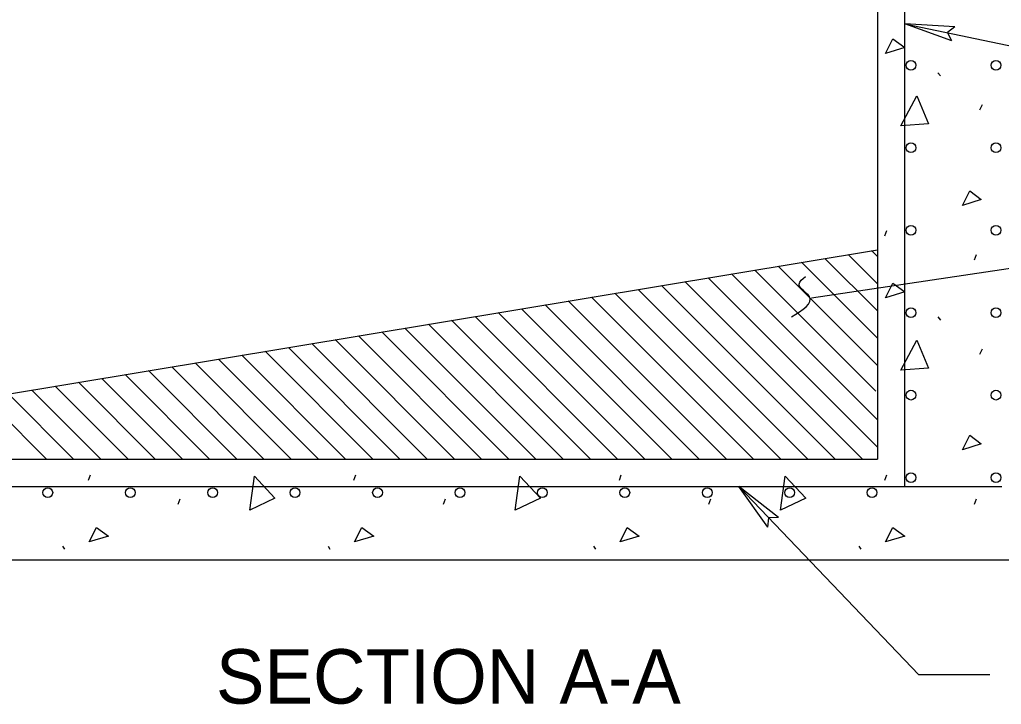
# Model space of a CAD drawing. Extents: x 0.9 to 8.1, y 0.4 to 10.5.
# Drawn here: x 1.927 to 3.714, y 5.114 to 6.36 of the extents above; entities that cross this region are included whole.
import ezdxf

# ---------------------------------------------------------------- set-up
doc = ezdxf.new("R2010")
doc.units = 0
for name, color, linetype in [('DETL-DIMS', 7, 'Continuous'), ('DETL-LINE', 7, 'Continuous'), ('DETL-TITL', 7, 'Continuous')]:
    doc.layers.add(name, color=color, linetype=linetype)

msp = doc.modelspace()

# ---------------------------------------------------------------- linework, layer by layer
at = {"layer": 'DETL-DIMS'}
for p, q in [((3.624, 6.3212), (3.5386, 6.3525)), ((3.6294, 6.3469), (3.5386, 6.3525)), ((3.6294, 6.3469), (3.6157, 6.3364)), ((3.624, 6.3212), (3.6157, 6.3364)), ((3.3682, 5.8536), (3.7993, 5.9181)), ((3.2892, 5.4363), (3.2365, 5.5104)), ((3.3082, 5.4544), (3.2365, 5.5104)), ((3.2892, 5.4363), (3.2909, 5.4535)), ((3.3082, 5.4544), (3.2909, 5.4535)), ((3.6931, 5.1682), (3.5638, 5.1682))]:
    msp.add_line(p, q, dxfattribs=at)
for points in [[(3.5386, 6.3525), (3.9981, 6.2566)], [(3.2365, 5.5104), (3.5638, 5.1682)]]:
    msp.add_lwpolyline(points, dxfattribs=at)
msp.add_spline([(3.3322, 5.8193), (3.3646, 5.8562), (3.3458, 5.8788), (3.3578, 5.8924)], degree=3, dxfattribs=at)
at = {"layer": 'DETL-LINE'}
for p, q in [((3.4886, 7.1185), (3.4886, 5.5604)), ((3.5386, 5.5104), (3.5386, 7.1185)), ((3.5985, 6.2634), (3.6033, 6.2574)), ((3.6746, 6.1958), (3.6794, 6.2055)), ((3.5019, 5.9663), (3.5055, 5.976)), ((1.8221, 5.665), (3.4886, 5.9414)), ((3.4354, 5.9326), (3.4886, 5.8794)), ((3.4778, 5.9397), (3.4886, 5.9289)), ((3.6649, 5.9228), (3.6686, 5.9325)), ((3.3504, 5.9185), (3.4886, 5.7804)), ((3.3929, 5.9256), (3.4886, 5.8299)), ((3.2231, 5.8974), (3.4886, 5.6319)), ((3.2655, 5.9044), (3.4858, 5.6841)), ((3.308, 5.9115), (3.4886, 5.7309)), ((3.1382, 5.8833), (3.4611, 5.5604)), ((3.1806, 5.8904), (3.4886, 5.5824)), ((3.0108, 5.8622), (3.3126, 5.5604)), ((3.0533, 5.8692), (3.3621, 5.5604)), ((3.0957, 5.8763), (3.4116, 5.5604)), ((2.9259, 5.8481), (3.2136, 5.5604)), ((2.9684, 5.8551), (3.2631, 5.5604)), ((2.7985, 5.827), (3.0651, 5.5604)), ((2.841, 5.834), (3.1146, 5.5604)), ((2.8835, 5.841), (3.1641, 5.5604)), ((2.7136, 5.8129), (2.9661, 5.5604)), ((2.7561, 5.8199), (3.0156, 5.5604)), ((3.5985, 5.819), (3.6033, 5.8129)), ((2.5863, 5.7917), (2.8176, 5.5604)), ((2.6287, 5.7988), (2.8671, 5.5604)), ((2.6712, 5.8058), (2.9166, 5.5604)), ((2.5014, 5.7777), (2.7186, 5.5604)), ((2.5438, 5.7847), (2.7681, 5.5604)), ((2.374, 5.7565), (2.5701, 5.5604)), ((2.4165, 5.7636), (2.6196, 5.5604)), ((2.4589, 5.7706), (2.6691, 5.5604)), ((3.6746, 5.7514), (3.6794, 5.761)), ((2.2466, 5.7354), (2.4216, 5.5604)), ((2.2891, 5.7424), (2.4711, 5.5604)), ((2.3316, 5.7495), (2.5206, 5.5604)), ((2.1617, 5.7213), (2.3226, 5.5604)), ((2.2042, 5.7284), (2.3721, 5.5604)), ((2.0344, 5.7002), (2.1742, 5.5604)), ((2.0768, 5.7072), (2.2237, 5.5604)), ((2.1193, 5.7143), (2.2732, 5.5604)), ((1.9495, 5.6861), (2.0752, 5.5604)), ((1.9919, 5.6931), (2.1247, 5.5604)), ((1.8646, 5.672), (1.9762, 5.5604)), ((1.907, 5.679), (2.0257, 5.5604)), ((1.8221, 5.5604), (3.4886, 5.5604)), ((2.0526, 5.5219), (2.0562, 5.5315)), ((2.5357, 5.5219), (2.5393, 5.5315)), ((3.0188, 5.5219), (3.0224, 5.5315)), ((3.5019, 5.5219), (3.5055, 5.5315)), ((1.7721, 5.5104), (3.5386, 5.5104)), ((3.5386, 5.5104), (3.715, 5.5104)), ((2.2157, 5.4784), (2.2193, 5.4881)), ((2.6988, 5.4784), (2.7024, 5.4881)), ((3.1818, 5.4784), (3.1855, 5.4881)), ((3.6649, 5.4784), (3.6686, 5.4881)), ((2.0055, 5.4023), (2.0091, 5.3963)), ((2.4886, 5.4023), (2.4922, 5.3963)), ((2.9717, 5.4023), (2.9753, 5.3963)), ((3.4548, 5.4023), (3.4584, 5.3963))]:
    msp.add_line(p, q, dxfattribs=at)
for points in [[(1.5066, 6.3068), (1.5066, 7.1175), (3.7698, 7.1175), (3.7698, 5.3767), (1.5066, 5.3767), (1.5066, 5.5888)], [(3.5031, 6.2985), (3.5164, 6.325), (3.5381, 6.3093), (3.5031, 6.2985)], [(3.5309, 6.1668), (3.5599, 6.2212), (3.5816, 6.1704), (3.5309, 6.1668)], [(3.6432, 6.0219), (3.6565, 6.0485), (3.677, 6.0328), (3.6432, 6.0219)], [(3.5031, 5.854), (3.5164, 5.8806), (3.5381, 5.8649), (3.5031, 5.854)], [(3.5309, 5.7224), (3.5599, 5.7767), (3.5816, 5.726), (3.5309, 5.7224)], [(3.6432, 5.5774), (3.6565, 5.604), (3.677, 5.5883), (3.6432, 5.5774)], [(2.3461, 5.4675), (2.3546, 5.5291), (2.392, 5.4893), (2.3461, 5.4675)], [(2.8292, 5.4675), (2.8376, 5.5291), (2.8751, 5.4893), (2.8292, 5.4675)], [(3.3123, 5.4675), (3.3207, 5.5291), (3.3582, 5.4893), (3.3123, 5.4675)], [(2.0538, 5.4096), (2.0671, 5.4361), (2.0889, 5.4204), (2.0538, 5.4096)], [(2.5369, 5.4096), (2.5502, 5.4361), (2.5719, 5.4204), (2.5369, 5.4096)], [(3.02, 5.4096), (3.0333, 5.4361), (3.055, 5.4204), (3.02, 5.4096)], [(3.5031, 5.4096), (3.5164, 5.4361), (3.5381, 5.4204), (3.5031, 5.4096)]]:
    msp.add_lwpolyline(points, dxfattribs=at)
for centre in [(3.5495, 6.2768), (3.7041, 6.2768), (3.5495, 6.1268), (3.7041, 6.1268), (3.5495, 5.9768), (3.7041, 5.9768), (3.5495, 5.8268), (3.7041, 5.8268), (3.5495, 5.6768), (3.7041, 5.6768), (3.5495, 5.5268), (3.7041, 5.5268), (1.9787, 5.4995), (2.1287, 5.4995), (2.2787, 5.4995), (2.4287, 5.4995), (2.5787, 5.4995), (2.7287, 5.4995), (2.8787, 5.4995), (3.0287, 5.4995), (3.1787, 5.4995), (3.3287, 5.4995), (3.4787, 5.4995)]:
    msp.add_circle(centre, 0.00888, dxfattribs=at)

# ---------------------------------------------------------------- texts
at = {"layer": 'DETL-TITL'}
msp.add_text('SECTION A-A', height=0.099, dxfattribs=at).set_placement((2.2847, 5.1156))

doc.saveas('drawing.dxf')
